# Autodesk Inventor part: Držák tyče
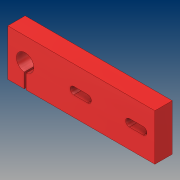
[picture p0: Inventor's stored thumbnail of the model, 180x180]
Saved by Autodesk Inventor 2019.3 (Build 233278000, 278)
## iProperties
Created: 2019-03
Part Number: Držák tyče
Material: Ocel, litá
Document SubType Name: Modeling
Designer: B-hon
Density: 7.85 g/cm^3
Appearance: Světle červená
Author: B-hon
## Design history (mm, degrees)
sketch "Náčrt1"
  geometry: L1 (36, 17.046)-(36, -20.998); L2 (-15, 20)-(106, 20); L3 (106, 20)-(106, -20); L4 (106, -20)-(-15, -20); L5 (-15, -20)-(-15, 20); C1 r 7.5 at (0, 0); 1 further point
  constraints: 10 end point, 2 parallel, 1 centre point, 1 coincident, 1 horizontal, 1 perpendicular, 1 vertical
  dimensions: "d0" = 15 diameter of C1; "d1" = 36 distance from line of C1.centre L1; "d2" = 15 distance from line of C1.centre L5; "d3" = 20 distance from line of C1.centre L2; "d4" = 20 distance from line of L4 C1.centre; "d5" = 70 distance between parallel lines of L3 L1
extrude "Vysunutí1" new body sketch "Náčrt1" distance "d6" = 15; taper "d7" = 0 deg
sketch "Náčrt2"
  geometry: L1 (0.75, -26.664)-(-0.75, -26.664); L2 (-0.75, -26.664)-(-0.75, -0.368); L3 (-0.75, -0.368)-(0.75, -0.368); L4 (0.75, -0.368)-(0.75, -26.664); 1 further point
  constraints: 8 end point, 2 parallel, 1 horizontal, 1 perpendicular
  dimensions: "d8" = 1.5 distance of L1.start L1.end; "d9" = 0.75 distance from line of point (0, 0) L2
extrude "Vysunutí2" cut sketch "Náčrt2" distance "d10" = 15; taper "d11" = 0 deg
sketch "Náčrt3"
  geometry: L1 (0, 0)-(15, 0) reference; L2 (15, 40)-(15, 0) reference; 2 further points
  dimensions: "d12" = 7.5 distance from line of L1 point (7.5, 7.5); "d13" = 7.5 distance from line of L2 point (7.5, 7.5)
hole "Díra1" sketch "Náčrt3" at (7.5, 7.5) diameter "d14" = 4.917; stored, may be unused: countersink angle "d18" = 90 deg, drill point angle "d20" = 118 deg; dims "d15" = 20, "d16" = 11, "d17" = 4.5, "d19" = 30
sketch "Náčrt4"
  geometry: L1 (106, -20)-(106, 20) reference; L2 (54, 0)-(42, 0); L3 (54, 3.2)-(42, 3.2); L4 (42, -3.2)-(54, -3.2); L5 (102, 0)-(90, 0); L6 (102, 3.2)-(90, 3.2); L7 (90, -3.2)-(102, -3.2); A1 r 7.5 centre (0, 0) between (0.75, -7.462) and (-0.75, -7.462) reference; A2 r 3.2 centre (54, 0) between (54, -3.2) and (54, 3.2); A3 r 3.2 centre (42, 0) between (42, 3.2) and (42, -3.2); A4 r 3.2 centre (102, 0) between (102, -3.2) and (102, 3.2); A5 r 3.2 centre (90, 0) between (90, 3.2) and (90, -3.2); 3 further points
  constraints: 16 end point, 8 point on circle, 8 tangent, 4 centre point, 2 horizontal, 2 midpoint, 2 parallel
  dimensions: "d21" = 48 distance of point (48, 0) A1.centre; "d22" = 10 distance from line of L1 point (96, 0); "d30" = 6 distance of point (48, 0) L2.end; "d31" = 6.4 diameter of A3; "d32" = 6 distance of point (96, 0) L5.end; "d33" = 6.4 diameter of A5
extrude "Vysunutí3" cut sketch "Náčrt4" extent not by distance; stored distance "d34" = 10; taper "d35" = 0 deg
node "Upravit přímo1"
node "Těleso1"
feature "Posunout1" dims "d38" = 6
other parameters: "d36" = 0, "d37" = 0
